(* Logix 5000 project; controller ACS_AddOnExample vendor 1 type 14 code 87 rev 20.12; software revision 20.01 *)
// Example Program to demonstrate ACS Drive with Add On Instructions

TASK MainTask (continuous, watchdog 500 ms) : MainProgram

MODULES
   Controller : vendor 1 type 14 code 87 (CompactLogixL23E_QB1_Controller 0, rev 20.12)
      LocalENB : vendor 1 type 12 code 190 (CompactLogixL23E_QB1_Ethernet 1, rev 20.11)
         ACS_DRIVE01 : vendor 1230 type 43 code 9046 (Ethernet 192.168.0.100, rev 2.37, StandardDataDriven RPI 20 ms)
      Local : CompactBus (CompactVirtualAdapter 3, rev 20.11)
         Discrete_Inputs : vendor 1 type 7 code 320 (Compact 1, rev 3.1, Input RPI 20 ms)
         Discrete_Outputs : vendor 1 type 7 code 322 (Compact 2, rev 3.1, Output RPI 20 ms)
END_MODULES

TYPE DriveFaults :
STRUCT
   Positive_Limit : BOOL;   // Positive Limit
   Negative_Limit : BOOL;   // Negative Limit
   E_Stop : BOOL;   // E Stop
   Position_Error : BOOL;   // Position Error
   Feedback_Error : BOOL;   // Feedback Error
   Over_Current : BOOL;   // Overcurrent
   Motor_Over_Temperature : BOOL;   // Motor Over Temperature
   Drive_Over_Temperature : BOOL;   // Drive Over Temperature
   Drive_Over_Voltage : BOOL;   // Drive Over Voltage
   Drive_Under_Voltage : BOOL;   // Drive Under Voltage
   Flash_Error : BOOL;   // Flash Error
   I2T_Limit : BOOL;   // I2T Limit Fault
   Short_Circuit : BOOL;   // Short Circuit Fault
   Watchdog_Reset : BOOL;   // Watchdog Reset
END_STRUCT
END_TYPE

TYPE DriveStatus :
STRUCT
   Drive_Enable : BOOL;   // Drive Enable Input
   Drive_Homed : BOOL;   // Drive Home Input
   Drive_InMotion : BOOL;   // Drive In Motion Input
   Drive_EStop : BOOL;   // Drive E-Stop Input
   rsved_bit00 : BOOL;
   rsved_bit01 : BOOL;
   rsved_bit02 : BOOL;
   rsved_bit03 : BOOL;
   rsved_bit04 : BOOL;
   rsved_bit05 : BOOL;
   rsved_bit06 : BOOL;
   rsved_bit07 : BOOL;
   rsved_bit08 : BOOL;
   Drive_EthAvail : BOOL;   // Drive Ethernet Online
   rsved_bit09 : BOOL;
   rsved_bit10 : BOOL;
   rsved_bit11 : BOOL;
   rsved_bit12 : BOOL;
   rsved_bit13 : BOOL;
   rsved_bit14 : BOOL;
   Drive_BrakeOff : BOOL;   // Brake Output (0 - Enabled; 1- Not Enabled)
   rsved_bit15 : BOOL;
   rsved_bit16 : BOOL;
   rsved_bit17 : BOOL;
   rsrved_bit18 : BOOL;
   rsrved_bit19 : BOOL;
   rsrved_bit20 : BOOL;
   rsrved_bit21 : BOOL;
   rsrved_bit22 : BOOL;
   rsrved_bit23 : BOOL;
   rsrved_bit24 : BOOL;
   Drive_Control : BOOL;
END_STRUCT
END_TYPE

ADD_ON_INSTRUCTION ACS_ABSOLUTE_MOVE   (* revision 2.0, vendor Tolomatic, Inc *)
// Move to an Absolute Position
VAR_INPUT
   Position : REAL; {required}   // Absolute Position
   Acceleration : REAL; {required}   // Trajectory Acceleration
   Deceleration : REAL; {required}   // Trajectory Deceleration
   Velocity : REAL; {required}   // Trajectory Constant Velocity
   Force : REAL; {required}   // Force Limit (Percent)
END_VAR
VAR_IN_OUT
   DriveMoveSelect : SINT; {required}   // ACS.O.MOVESELECT
   DriveTargetPos : REAL; {required}   // ACS.O.TARGET_0_POS
   DriveTargetVel : REAL; {required}   // ACS.O.TARGET_0_VEL
   DriveTargetAcc : REAL; {required}   // ACS.O.TARGET_0_ACC
   DriveTargetDec : REAL; {required}   // ACS.O.TARGET_0_DEC
   DriveTargetForce : REAL; {required}   // ACS.O.TARGET_0_FORCE
   DriveTargetMotionType : DINT; {required}   // ACS.O.TARGET_0_MOTION_TYPE
END_VAR

ROUTINE Logic   (* ladder *)
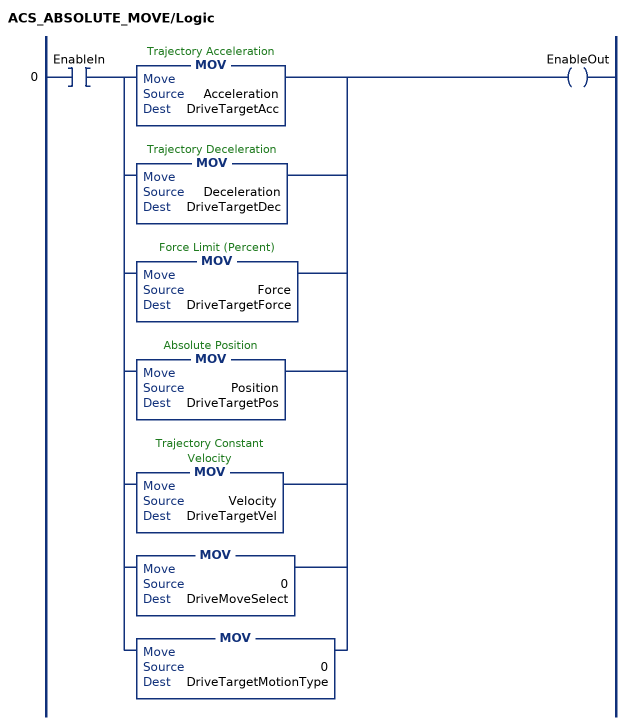
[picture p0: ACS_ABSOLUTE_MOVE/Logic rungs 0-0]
   0: XIC(EnableIn)[MOV(Acceleration,DriveTargetAcc) ,MOV(Deceleration,DriveTargetDec) ,MOV(Force,DriveTargetForce) ,MOV(Position,DriveTargetPos) ,MOV(Velocity,DriveTargetVel) ,MOV(0,DriveMoveSelect) ,MOV(0,DriveTargetMotionType) ]OTE(EnableOut);
END_ROUTINE
END_ADD_ON_INSTRUCTION

ADD_ON_INSTRUCTION ACS_CLEAR_START_MOTION   (* revision 2.0, vendor Tolomatic, Inc *)
// Clears the Start Motion Bit
// Clears Start Motion Timer Enable Line
// Resets Start Motion Timer Accumulator
VAR_IN_OUT
   DriveCMD : SINT; {required}   // ACS.O.CMD
   SMTimerEnable : BOOL; {required}   // Start Motion Timer Enable Line
   SMTimer : TIMER; {required}   // Start Motion Timer
END_VAR
VAR
   OutMask : DINT; {access None}   // Mask used to clear start motion bit
END_VAR

ROUTINE Logic   (* ladder *)
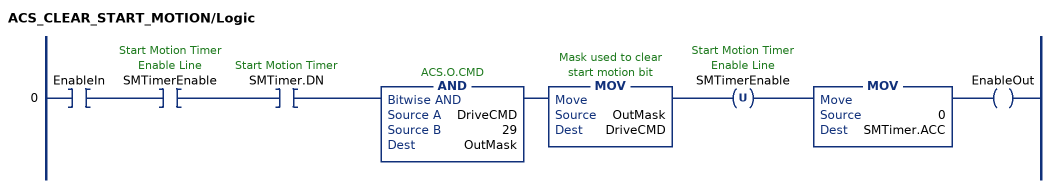
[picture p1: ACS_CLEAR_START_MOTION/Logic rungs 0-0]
   0: XIC(EnableIn)XIC(SMTimerEnable)XIC(SMTimer.DN)AND(DriveCMD,29,OutMask)MOV(OutMask,DriveCMD)OTU(SMTimerEnable)MOV(0,SMTimer.ACC)OTE(EnableOut);
END_ROUTINE
END_ADD_ON_INSTRUCTION

ADD_ON_INSTRUCTION ACS_DISABLE_DRIVE   (* revision 2.0, vendor Tolomatic, Inc *)
// Disable ACS Drive
VAR_IN_OUT
   DriveCMD : SINT; {required}   // ToloOutput Reference
END_VAR

ROUTINE Logic   (* ladder *)
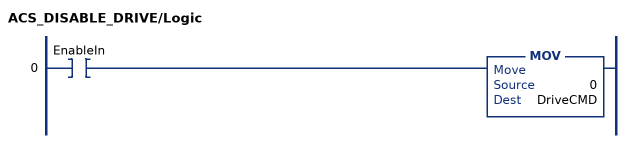
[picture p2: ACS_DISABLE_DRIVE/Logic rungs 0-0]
   0: XIC(EnableIn)MOV(0,DriveCMD);
END_ROUTINE
END_ADD_ON_INSTRUCTION

ADD_ON_INSTRUCTION ACS_ENABLE_DRIVE   (* revision 2.0, vendor Tolomatic, Inc *)
// Enable ACS Drive
VAR_IN_OUT
   DriveCMD : SINT; {required}   // ToloOutput Reference
END_VAR

ROUTINE Logic   (* ladder *)
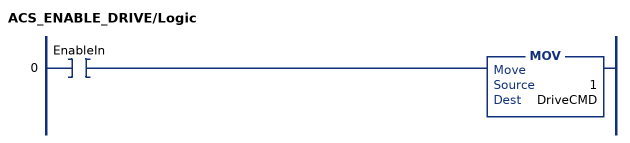
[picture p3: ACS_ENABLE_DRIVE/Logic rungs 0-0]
   0: XIC(EnableIn)MOV(1,DriveCMD);
END_ROUTINE
END_ADD_ON_INSTRUCTION

ADD_ON_INSTRUCTION ACS_FAULTS_ACTIVE   (* revision 2.0, vendor Tolomatic, Inc *)
// True if ACS Drive contains any faults
VAR_IN_OUT
   DriveFaults : DINT; {required}   // ACS.I.FAULTS
END_VAR
VAR
   LocalFaults : DriveFaults; {access None}   // Local Mapping for faults
END_VAR

ROUTINE Logic   (* ladder *)
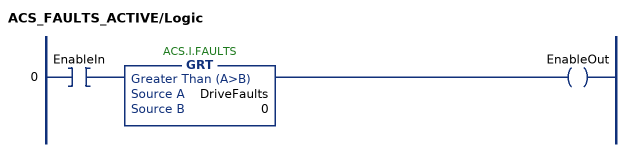
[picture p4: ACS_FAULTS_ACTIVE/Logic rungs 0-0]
   0: XIC(EnableIn)GRT(DriveFaults,0)OTE(EnableOut);
END_ROUTINE
END_ADD_ON_INSTRUCTION

ADD_ON_INSTRUCTION ACS_FAULTS_CRITICAL_ACTIVE   (* revision 2.0, vendor Tolomatic, Inc *)
// Determines if ACS drive has any Critical Faults active
VAR_IN_OUT
   DriveFaults : DINT; {required}   // ACS.I.FAULTS
END_VAR
VAR
   LocalFaults : DriveFaults; {access None}   // Local Storage for decoding faults
END_VAR

ROUTINE Logic   (* ladder *)
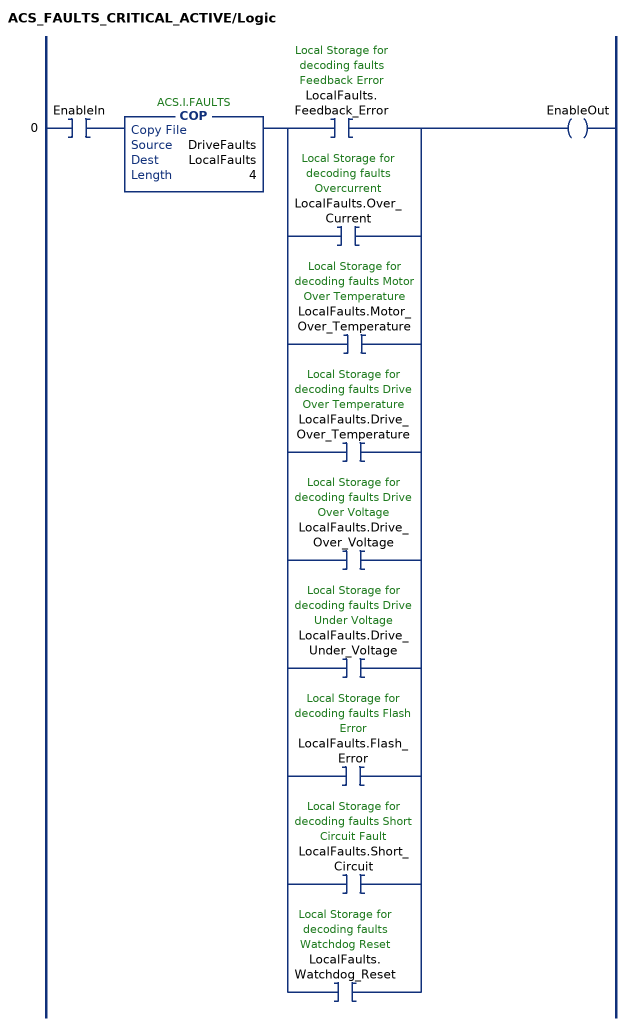
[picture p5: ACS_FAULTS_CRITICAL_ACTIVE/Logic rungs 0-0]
   0: XIC(EnableIn)COP(DriveFaults,LocalFaults,4)[XIC(LocalFaults.Feedback_Error) ,XIC(LocalFaults.Over_Current) ,XIC(LocalFaults.Motor_Over_Temperature) ,XIC(LocalFaults.Drive_Over_Temperature) ,XIC(LocalFaults.Drive_Over_Voltage) ,XIC(LocalFaults.Drive_Under_Voltage) ,XIC(LocalFaults.Flash_Error) ,XIC(LocalFaults.Short_Circuit) ,XIC(LocalFaults.Watchdog_Reset) ]OTE(EnableOut);
END_ROUTINE
END_ADD_ON_INSTRUCTION

ADD_ON_INSTRUCTION ACS_FAULTS_SAFETY_ACTIVE   (* revision 2.0, vendor Tolomatic, Inc *)
// True if ACS Drive contains any safety faults
VAR_IN_OUT
   DriveFaults : DINT; {required}   // ACS.I.FAULTS
END_VAR
VAR
   LocalFaults : DriveFaults; {access None}   // Local storage for faults
END_VAR

ROUTINE Logic   (* ladder *)
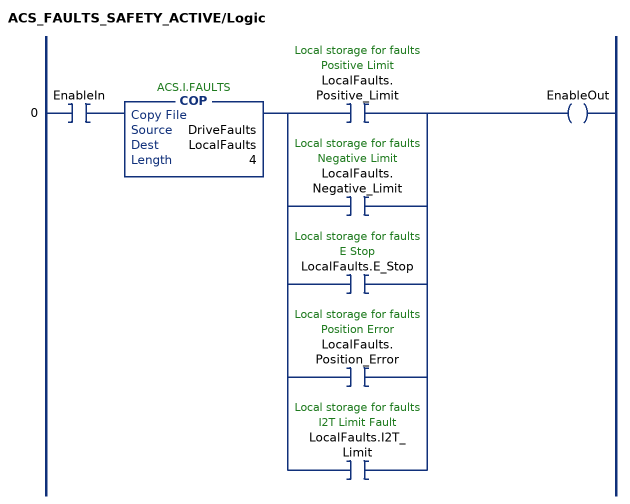
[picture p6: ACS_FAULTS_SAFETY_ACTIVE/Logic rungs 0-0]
   0: XIC(EnableIn)COP(DriveFaults,LocalFaults,4)[XIC(LocalFaults.Positive_Limit) ,XIC(LocalFaults.Negative_Limit) ,XIC(LocalFaults.E_Stop) ,XIC(LocalFaults.Position_Error) ,XIC(LocalFaults.I2T_Limit) ]OTE(EnableOut);
END_ROUTINE
END_ADD_ON_INSTRUCTION

ADD_ON_INSTRUCTION ACS_FORCE_MOVE   (* revision 2.0, vendor Tolomatic, Inc *)
// Move to an Absolute Position using Force Move logic
VAR_INPUT
   Position : REAL; {required}   // Absolute Position
   Acceleration : REAL; {required}   // Trajectory Acceleration
   Deceleration : REAL; {required}   // Trajectory Deceleration
   Velocity : REAL; {required}   // Trajectory Constant Velocity
   Force : REAL; {required}   // Force Limit (Percent)
END_VAR
VAR_IN_OUT
   DriveMoveSelect : SINT; {required}   // ACS.O.MOVESELECT
   DriveTargetPos : REAL; {required}   // ACS.O.TARGET_0_POS
   DriveTargetVel : REAL; {required}   // ACS.O.TARGET_0_VEL
   DriveTargetAcc : REAL; {required}   // ACS.O.TARGET_0_ACC
   DriveTargetDec : REAL; {required}   // ACS.O.TARGET_0_DEC
   DriveTargetForce : REAL; {required}   // ACS.O.TARGET_0_FORCE
   DriveTargetMotionType : DINT; {required}   // ACS.O.TARGET_0_MOTION_TYPE
END_VAR

ROUTINE Logic   (* ladder *)
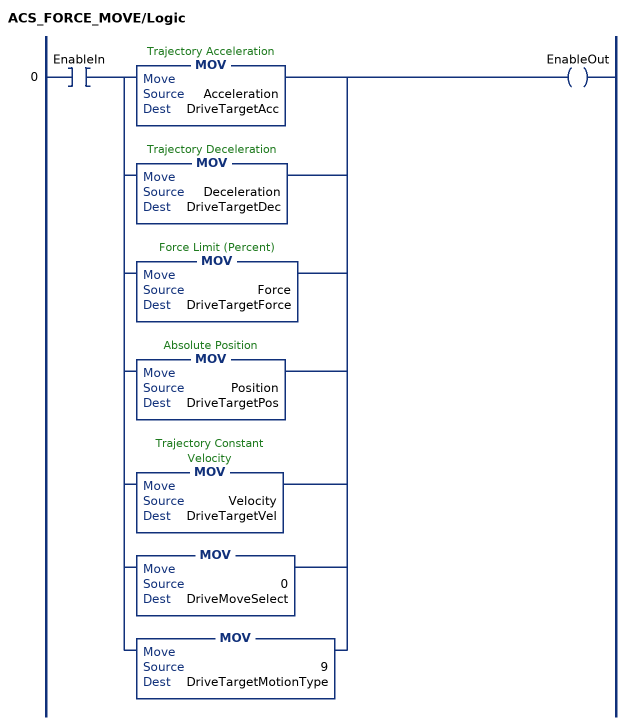
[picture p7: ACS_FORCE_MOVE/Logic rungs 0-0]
   0: XIC(EnableIn)[MOV(Acceleration,DriveTargetAcc) ,MOV(Deceleration,DriveTargetDec) ,MOV(Force,DriveTargetForce) ,MOV(Position,DriveTargetPos) ,MOV(Velocity,DriveTargetVel) ,MOV(0,DriveMoveSelect) ,MOV(9,DriveTargetMotionType) ]OTE(EnableOut);
END_ROUTINE
END_ADD_ON_INSTRUCTION

ADD_ON_INSTRUCTION ACS_HOME_MOVE   (* revision 2.0, vendor Tolomatic, Inc *)
// Initiated Homing Routine based on homing profile defined in drive
// Help:
// Add-On Instruction Executes Homing Routine
VAR_IN_OUT
   DriveCMD : SINT; {required}   // ACS.O.CMD
END_VAR

ROUTINE Logic   (* ladder *)
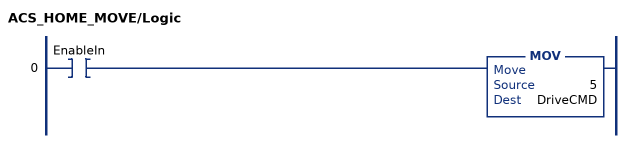
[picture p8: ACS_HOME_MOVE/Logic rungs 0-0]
   0: XIC(EnableIn)MOV(5,DriveCMD);
END_ROUTINE
END_ADD_ON_INSTRUCTION

ADD_ON_INSTRUCTION ACS_INCREMENTAL_MOVE   (* revision 2.0, vendor Tolomatic, Inc *)
// Move to a position relative to current position
VAR_INPUT
   Distance : REAL; {required}   // Distance to Travel (Positive or Negative)
   Acceleration : REAL; {required}   // Trajectory Acceleration
   Deceleration : REAL; {required}   // Trajectory Deceleration
   Velocity : REAL; {required}   // Trajectory Constance Velocity
   Force : REAL; {required}   // Force Limit (Percent)
END_VAR
VAR_IN_OUT
   DriveMoveSelect : SINT; {required}   // ACS.O.MOVESELECT
   DriveTargetAcc : REAL; {required}   // ACS.O.TARGET_0_ACC
   DriveTargetDec : REAL; {required}   // ACS.O.TARGET_0_DEC
   DriveTargetForce : REAL; {required}   // ACS.O.TARGET_0_FORCE
   DriveTargetMotionType : DINT; {required}   // ACS.O.TARGET_0_MOTION_TYPE
   DriveTargetPos : REAL; {required}   // ACS.O.TARGET_0_POS
   DriveTargetVel : REAL; {required}   // ACS.O.TARGET_0_VEL
END_VAR
VAR
   AbsDistance : REAL; {access None}   // Absolute Value of Distance Input
END_VAR

ROUTINE Logic   (* ladder *)
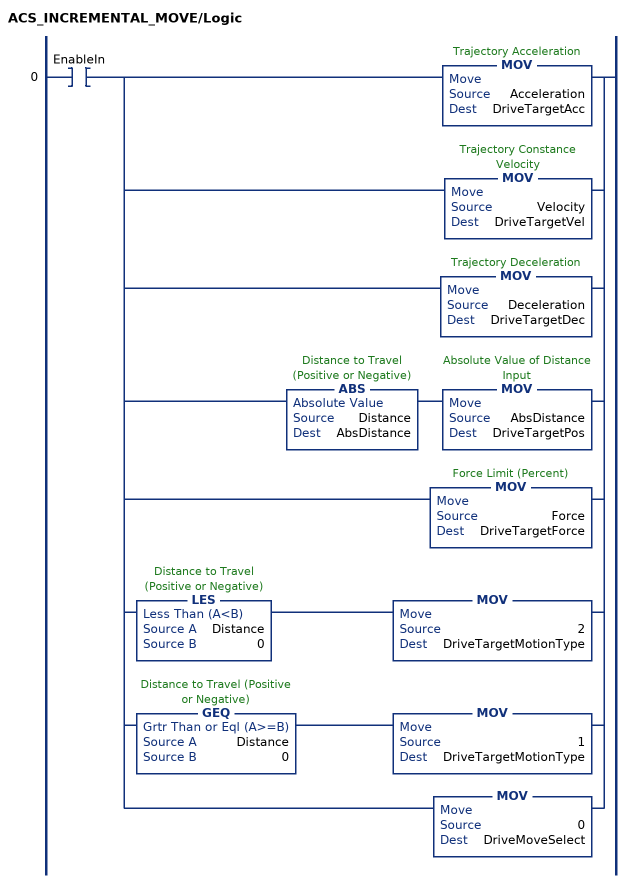
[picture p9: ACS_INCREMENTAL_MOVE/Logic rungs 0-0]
   0: XIC(EnableIn)[MOV(Acceleration,DriveTargetAcc) ,MOV(Velocity,DriveTargetVel) ,MOV(Deceleration,DriveTargetDec) ,ABS(Distance,AbsDistance) MOV(AbsDistance,DriveTargetPos) ,MOV(Force,DriveTargetForce) ,LES(Distance,0) MOV(2,DriveTargetMotionType) ,GEQ(Distance,0) MOV(1,DriveTargetMotionType) ,MOV(0,DriveMoveSelect) ];
END_ROUTINE
END_ADD_ON_INSTRUCTION

ADD_ON_INSTRUCTION ACS_INDEXED_MOVE   (* revision 2.0, vendor Tolomatic, Inc *)
// Execute a saved indexed move as defined in the drive
VAR_IN_OUT
   DriveMoveSelect : SINT; {required}   // ACS.0.MOVESELECT
END_VAR
VAR_INPUT
   Index : INT; {required}   // Move Index to Execute
END_VAR

ROUTINE Logic   (* ladder *)
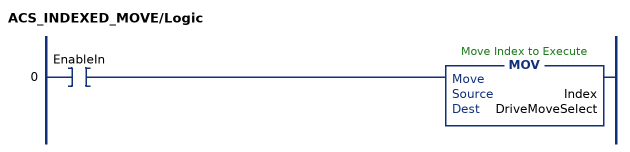
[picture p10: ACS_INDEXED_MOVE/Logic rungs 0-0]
   0: XIC(EnableIn)MOV(Index,DriveMoveSelect);
END_ROUTINE
END_ADD_ON_INSTRUCTION

ADD_ON_INSTRUCTION ACS_SET_DIGITAL_OUTPUTS   (* revision 2.0, vendor Tolomatic, Inc *)
// Set Digital Output Bits on ACS Drive and Controller
VAR_IN_OUT
   DriveDigitalOutput : DINT; {required}   // ACS.0.DIGITAL_OUTPUT
END_VAR
VAR_INPUT
   DigitalOutput1 : BOOL; {visible}   // Digital Output 1
   DigitalOutput2 : BOOL; {visible}   // Digital Output 2
   DigitalOutput3 : BOOL; {visible}   // Digital Output 3
   DigitalOutput4 : BOOL; {visible}   // Digital Output 4
END_VAR
VAR
   DigitalOutputs : DINT; {access None}   // Combined value of the digital inputs
END_VAR

ROUTINE Logic   (* ladder *)
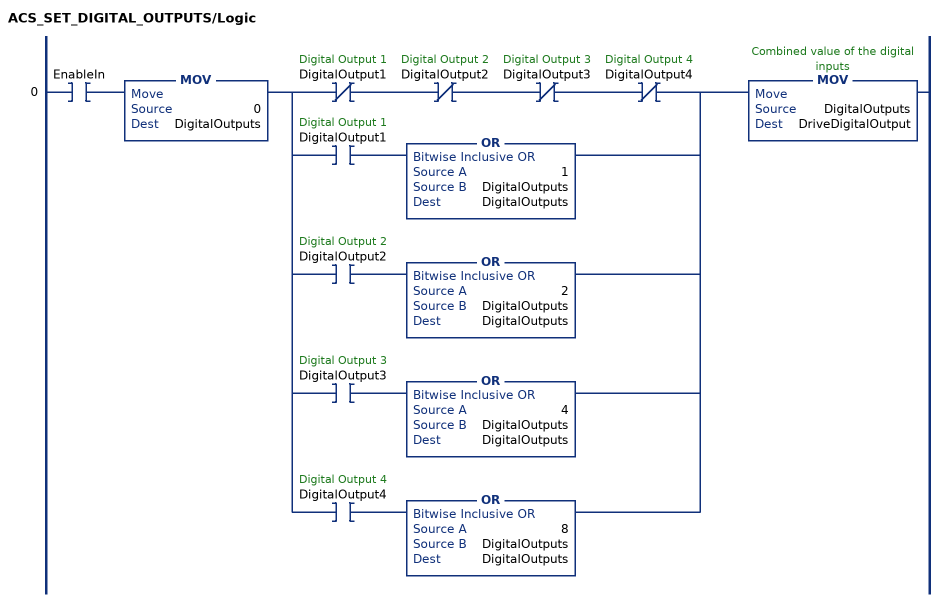
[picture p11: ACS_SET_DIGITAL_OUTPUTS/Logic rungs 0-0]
   0: XIC(EnableIn)MOV(0,DigitalOutputs)[XIO(DigitalOutput1) XIO(DigitalOutput2) XIO(DigitalOutput3) XIO(DigitalOutput4) ,XIC(DigitalOutput1) OR(1,DigitalOutputs,DigitalOutputs) ,XIC(DigitalOutput2) OR(2,DigitalOutputs,DigitalOutputs) ,XIC(DigitalOutput3) OR(4,DigitalOutputs,DigitalOutputs) ,XIC(DigitalOutput4) OR(8,DigitalOutputs,DigitalOutputs) ]MOV(DigitalOutputs,DriveDigitalOutput);
END_ROUTINE
END_ADD_ON_INSTRUCTION

ADD_ON_INSTRUCTION ACS_SOFTWARE_STOP   (* revision 2.0, vendor Tolomatic, Inc *)
// Sends a network ESTOP command
VAR_IN_OUT
   DriveCMD : SINT; {required}   // ACS.O.CMD
END_VAR

ROUTINE Logic   (* ladder *)
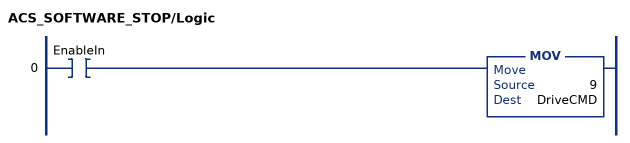
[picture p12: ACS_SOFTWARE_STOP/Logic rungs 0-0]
   0: XIC(EnableIn)MOV(9,DriveCMD);
END_ROUTINE
END_ADD_ON_INSTRUCTION

ADD_ON_INSTRUCTION ACS_START_MOTION   (* revision 2.0, vendor Tolomatic, Inc *)
VAR_IN_OUT
   DriveCMD : SINT; {required}   // ACS.O.CMD
END_VAR
VAR_INPUT
   PulseWidth : DINT := 200; {visible}   // Time to hold Start Motion bit High in Milliseconds. **This should be greater than the RPI of the drive
END_VAR
VAR_IN_OUT
   StartMotionTimer : TIMER; {required}   // Timer to hold Start Motion Bit High
   SMTimerEnable : BOOL; {required}   // Enable Line for Start Motion Timer
END_VAR

ROUTINE Logic   (* ladder *)
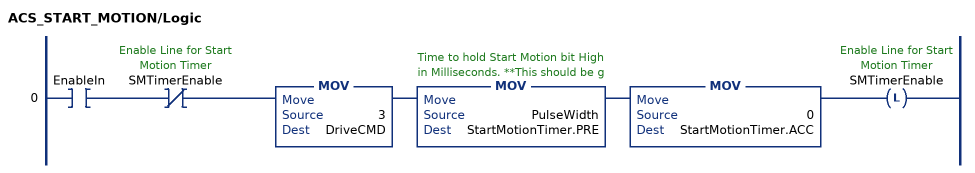
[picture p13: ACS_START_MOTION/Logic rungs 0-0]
   0: XIC(EnableIn)XIO(SMTimerEnable)MOV(3,DriveCMD)MOV(PulseWidth,StartMotionTimer.PRE)MOV(0,StartMotionTimer.ACC)OTL(SMTimerEnable);
END_ROUTINE
END_ADD_ON_INSTRUCTION

ADD_ON_INSTRUCTION ACS_STOP_MOTION   (* revision 2.0, vendor Tolomatic, Inc *)
// Stops ACS Drive Motion
VAR_IN_OUT
   DriveCMD : SINT; {required}   // ACS.O.CMD
END_VAR

ROUTINE Logic   (* ladder *)
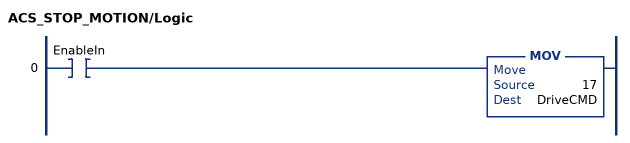
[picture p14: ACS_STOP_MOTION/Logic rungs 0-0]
   0: XIC(EnableIn)MOV(17,DriveCMD);
END_ROUTINE
END_ADD_ON_INSTRUCTION

PROGRAM MainProgram   (* main routine MainRoutine *)
VAR
   DRV_ABS_MOVE_AOI : ACS_ABSOLUTE_MOVE;
   DRV_CLR_START_MOT_AOI : ACS_CLEAR_START_MOTION;
   DRV_DISABLE_AOI : ACS_DISABLE_DRIVE;
   DRV_DOUT_AOI : ACS_SET_DIGITAL_OUTPUTS;
   DRV_ENABLE_AOI : ACS_ENABLE_DRIVE;
   DRV_FAULTS_AOI : ACS_FAULTS_ACTIVE;
   DRV_FAULTS_CRIT_AOI : ACS_FAULTS_CRITICAL_ACTIVE;
   DRV_FAULTS_SAFE_AOI : ACS_FAULTS_SAFETY_ACTIVE;
   DRV_FORCE_MOVE_AOI : ACS_FORCE_MOVE;
   DRV_HOME_AOI : ACS_HOME_MOVE;
   DRV_INC_MOT_AOI : ACS_INCREMENTAL_MOVE;
   DRV_INDEX_MOVE_AOI : ACS_INDEXED_MOVE;
   DRV_START_MOT_AOI : ACS_START_MOTION := (PulseWidth := 50);
   DRV_STOP_MOT_AOI : ACS_STOP_MOTION;
   DRV_SWS_AOI : ACS_SOFTWARE_STOP;
   FAULTS_ACTIVE : BOOL;
   FAULTS_ACTIVE_CRIT : BOOL;
   FAULTS_ACTIVE_SAFE : BOOL;
   SMTimer : TIMER;
   SMTimerEn : BOOL;
   TEST_ABS_MOVE : BOOL;
   TEST_DIGITAL_OUTPUTS : BOOL;
   TEST_DISABLE : BOOL;
   TEST_ENABLE : BOOL;
   TEST_FORCE_MOVE : BOOL;
   TEST_HOME_MOVE : BOOL;
   TEST_INC_MOVE : BOOL;
   TEST_INDEXED_MOVE : BOOL;
   TEST_SOFTWARE_STOP : BOOL;
   TEST_STOP_MOTION : BOOL;
END_VAR

ROUTINE MainRoutine   (* ladder *)
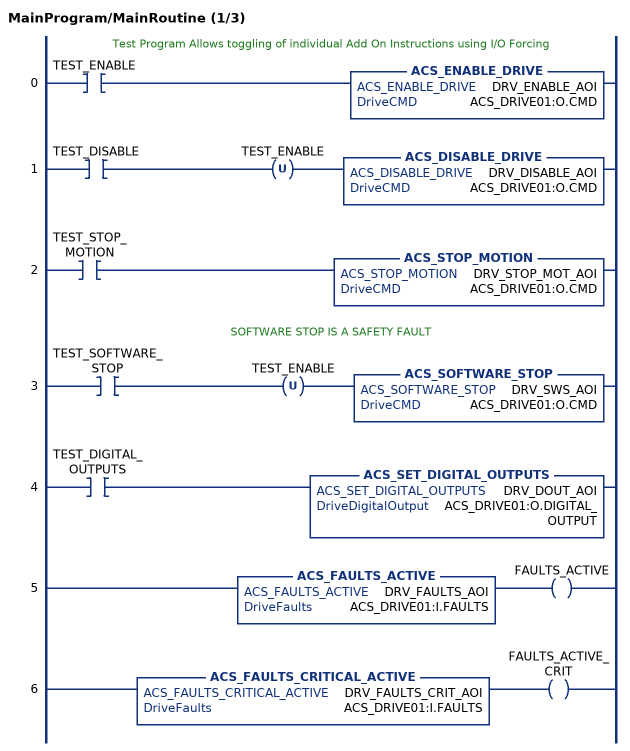
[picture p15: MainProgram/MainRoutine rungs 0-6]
   // Test Program Allows toggling of individual Add On Instructions using I/O Forcing
   0: XIC(TEST_ENABLE)ACS_ENABLE_DRIVE(DRV_ENABLE_AOI,ACS_DRIVE01:O.CMD);
   1: XIC(TEST_DISABLE)OTU(TEST_ENABLE)ACS_DISABLE_DRIVE(DRV_DISABLE_AOI,ACS_DRIVE01:O.CMD);
   2: XIC(TEST_STOP_MOTION)ACS_STOP_MOTION(DRV_STOP_MOT_AOI,ACS_DRIVE01:O.CMD);
   // SOFTWARE STOP IS A SAFETY FAULT
   3: XIC(TEST_SOFTWARE_STOP)OTU(TEST_ENABLE)ACS_SOFTWARE_STOP(DRV_SWS_AOI,ACS_DRIVE01:O.CMD);
   4: XIC(TEST_DIGITAL_OUTPUTS)ACS_SET_DIGITAL_OUTPUTS(DRV_DOUT_AOI,ACS_DRIVE01:O.DIGITAL_OUTPUT);
   5: ACS_FAULTS_ACTIVE(DRV_FAULTS_AOI,ACS_DRIVE01:I.FAULTS)OTE(FAULTS_ACTIVE);
   6: ACS_FAULTS_CRITICAL_ACTIVE(DRV_FAULTS_CRIT_AOI,ACS_DRIVE01:I.FAULTS)OTE(FAULTS_ACTIVE_CRIT);
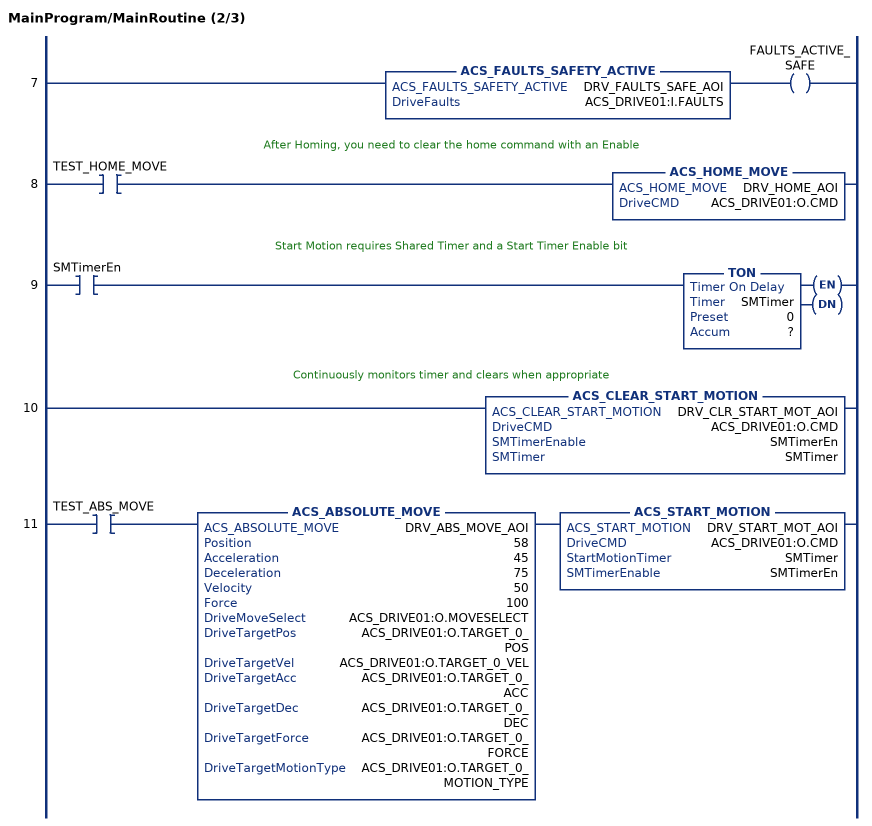
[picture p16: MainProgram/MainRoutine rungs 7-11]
   7: ACS_FAULTS_SAFETY_ACTIVE(DRV_FAULTS_SAFE_AOI,ACS_DRIVE01:I.FAULTS)OTE(FAULTS_ACTIVE_SAFE);
   // After Homing, you need to clear the home command with an Enable
   8: XIC(TEST_HOME_MOVE)ACS_HOME_MOVE(DRV_HOME_AOI,ACS_DRIVE01:O.CMD);
   // Start Motion requires Shared Timer and a Start Timer Enable bit
   9: XIC(SMTimerEn)TON(SMTimer,?,?);
   // Continuously monitors timer and clears when appropriate
   10: ACS_CLEAR_START_MOTION(DRV_CLR_START_MOT_AOI,ACS_DRIVE01:O.CMD,SMTimerEn,SMTimer);
   11: XIC(TEST_ABS_MOVE)ACS_ABSOLUTE_MOVE(DRV_ABS_MOVE_AOI,58,45,75,50,100,ACS_DRIVE01:O.MOVESELECT,ACS_DRIVE01:O.TARGET_0_POS,ACS_DRIVE01:O.TARGET_0_VEL,ACS_DRIVE01:O.TARGET_0_ACC,ACS_DRIVE01:O.TARGET_0_DEC,ACS_DRIVE01:O.TARGET_0_FORCE,ACS_DRIVE01:O.TARGET_0_MOTION_TYPE)ACS_START_MOTION(DRV_START_MOT_AOI,ACS_DRIVE01:O.CMD,SMTimer,SMTimerEn);
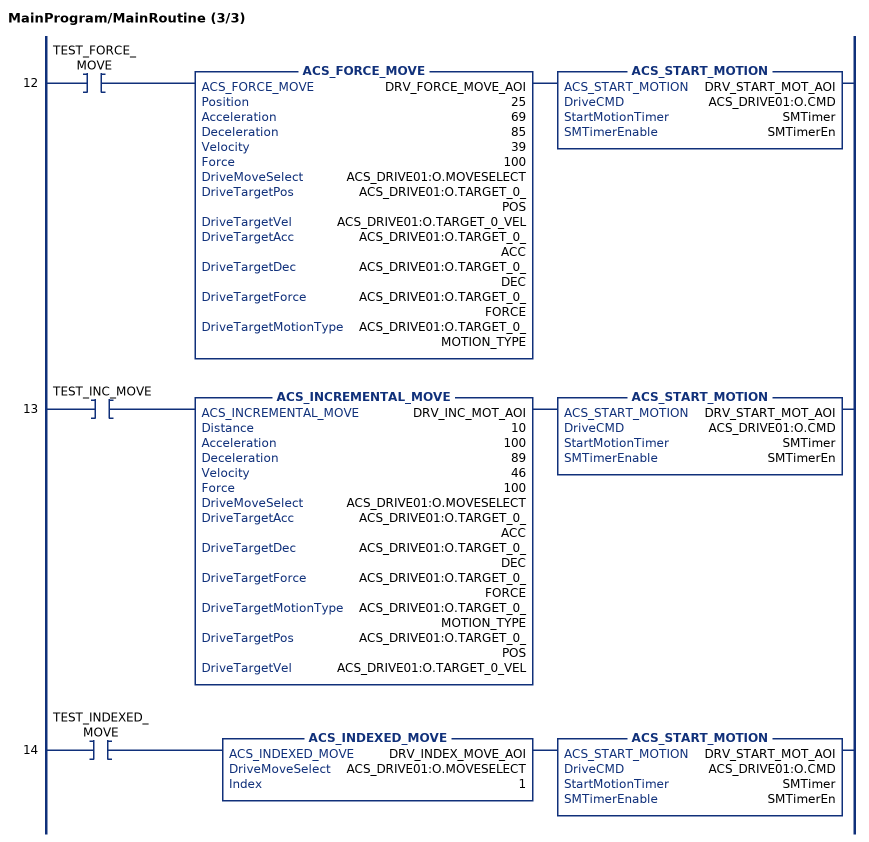
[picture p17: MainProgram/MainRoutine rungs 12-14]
   12: XIC(TEST_FORCE_MOVE)ACS_FORCE_MOVE(DRV_FORCE_MOVE_AOI,25,69,85,39,100,ACS_DRIVE01:O.MOVESELECT,ACS_DRIVE01:O.TARGET_0_POS,ACS_DRIVE01:O.TARGET_0_VEL,ACS_DRIVE01:O.TARGET_0_ACC,ACS_DRIVE01:O.TARGET_0_DEC,ACS_DRIVE01:O.TARGET_0_FORCE,ACS_DRIVE01:O.TARGET_0_MOTION_TYPE)ACS_START_MOTION(DRV_START_MOT_AOI,ACS_DRIVE01:O.CMD,SMTimer,SMTimerEn);
   13: XIC(TEST_INC_MOVE)ACS_INCREMENTAL_MOVE(DRV_INC_MOT_AOI,10,100,89,46,100,ACS_DRIVE01:O.MOVESELECT,ACS_DRIVE01:O.TARGET_0_ACC,ACS_DRIVE01:O.TARGET_0_DEC,ACS_DRIVE01:O.TARGET_0_FORCE,ACS_DRIVE01:O.TARGET_0_MOTION_TYPE,ACS_DRIVE01:O.TARGET_0_POS,ACS_DRIVE01:O.TARGET_0_VEL)ACS_START_MOTION(DRV_START_MOT_AOI,ACS_DRIVE01:O.CMD,SMTimer,SMTimerEn);
   14: XIC(TEST_INDEXED_MOVE)ACS_INDEXED_MOVE(DRV_INDEX_MOVE_AOI,ACS_DRIVE01:O.MOVESELECT,1)ACS_START_MOTION(DRV_START_MOT_AOI,ACS_DRIVE01:O.CMD,SMTimer,SMTimerEn);
END_ROUTINE
END_PROGRAM
